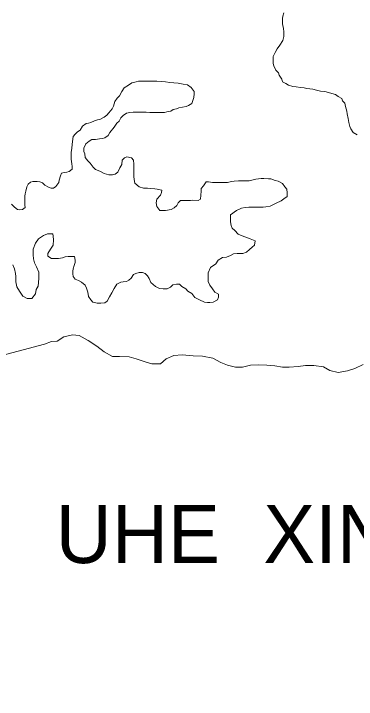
# Model space of a CAD drawing. Extents: x -1643653 to 4543381, y 1624270 to 13878484.
# Drawn here: x 627893 to 630834, y 8933841 to 8939733 of the extents above; entities that cross this region are included whole.
import ezdxf

# ---------------------------------------------------------------- set-up
doc = ezdxf.new("R2010")
doc.units = 0
doc.header["$LTSCALE"] = 200
for name, color, linetype, lineweight in [('25', 7, 'Continuous', 13), ('57', 7, 'Continuous', 13), ('60', 7, 'Continuous', 13)]:
    doc.layers.add(name, color=color, linetype=linetype, lineweight=lineweight)
doc.layers.add('42', color=7, linetype='Continuous')

msp = doc.modelspace()

# ---------------------------------------------------------------- linework, layer by layer
at = {"layer": '25'}
for points in [[(630842.4, 8938690.8), (630807.5, 8938711.1), (630787.8, 8938743.8), (630777.9, 8938763.8), (630770.7, 8938798.9), (630763.5, 8938834), (630756.3, 8938874.1), (630751.4, 8938896.7), (630741.7, 8938934.3), (630734.4, 8938964.4), (630714.6, 8938984.6), (630709.7, 8939004.6), (630677.4, 8939022.4), (630655, 8939040.1), (630625, 8939047.8), (630595.1, 8939055.5), (630562.6, 8939063.2), (630527.6, 8939068.4), (630492.7, 8939076.2), (630460.2, 8939083.9), (630410.3, 8939091.7), (630385.3, 8939096.9), (630355.3, 8939099.6), (630317.8, 8939104.9), (630287.8, 8939107.6), (630252.9, 8939120.3), (630228, 8939133), (630200.6, 8939148.2), (630193.3, 8939170.8), (630171, 8939206), (630166.2, 8939226), (630143.8, 8939248.7), (630126.6, 8939283.9), (630119.2, 8939304), (630119.5, 8939336.5), (630119.7, 8939364), (630137.5, 8939399), (630155.2, 8939431.4), (630178, 8939463.8), (630203.3, 8939503.7), (630211.1, 8939536.2), (630211.3, 8939573.7), (630209.1, 8939608.8), (630204.3, 8939628.8), (630199.4, 8939648.9), (630199.6, 8939668.9), (630199.7, 8939691.5), (630202.4, 8939711.5), (630212.6, 8939741.5)], [(627898.9, 8938069.4), (627926.2, 8938049.2), (627946.2, 8938049), (627968.8, 8938051.4), (627991.4, 8938068.8), (627989.1, 8938088.8), (627986.7, 8938111.4), (627986.9, 8938133.9), (627987.2, 8938166.4), (627989.8, 8938186.4), (627997.5, 8938208.9), (628005.3, 8938243.9), (628015.5, 8938268.9), (628035.6, 8938286.3), (628058.1, 8938291.2), (628093.2, 8938290.9), (628115.6, 8938288.3), (628140.6, 8938280.6), (628160.5, 8938260.4), (628190.3, 8938242.7), (628212.8, 8938232.5), (628232.8, 8938234.9), (628255.4, 8938247.3), (628280.7, 8938282.2), (628283.3, 8938302.2), (628293.6, 8938339.7), (628303.8, 8938362.1), (628326.4, 8938369.5), (628348.9, 8938371.8), (628368.9, 8938376.7), (628394.1, 8938396.6), (628394.3, 8938419.1), (628391.9, 8938441.7), (628389.6, 8938461.7), (628384.7, 8938481.8), (628384.9, 8938501.8), (628385.1, 8938524.3), (628385.2, 8938544.3), (628390.4, 8938574.3), (628393.2, 8938611.9), (628395.9, 8938631.9), (628401.1, 8938656.9), (628403.7, 8938676.9), (628421.4, 8938699.3), (628441.6, 8938716.7), (628461.7, 8938731.6), (628481.9, 8938766.5), (628514.6, 8938788.8), (628534.7, 8938793.7), (628554.7, 8938798.6), (628587.3, 8938813.4), (628612.4, 8938820.7), (628632.4, 8938823.1), (628670.1, 8938842.9), (628692.8, 8938860.2), (628710.4, 8938882.7), (628738.2, 8938915), (628748.4, 8938940), (628761.2, 8938977.5), (628781.4, 8939007.4), (628801.6, 8939027.3), (628821.9, 8939064.7), (628842.1, 8939097.1), (628877.3, 8939119.4), (628907.5, 8939139.2), (628942.6, 8939149), (628965.1, 8939153.9), (628990.1, 8939153.7), (629022.6, 8939153.5), (629062.6, 8939153.2), (629097.7, 8939153), (629122.7, 8939152.8), (629157.7, 8939150.1), (629195.2, 8939147.3), (629232.6, 8939142.1), (629267.6, 8939139.3), (629305.1, 8939136.6), (629347.6, 8939128.8), (629385, 8939121.1), (629417.4, 8939098.3), (629442.1, 8939065.6), (629442, 8939045.6), (629439.2, 8939013), (629431.6, 8938988.1), (629421.3, 8938960.6), (629393.7, 8938943.2), (629373.6, 8938935.9), (629341.1, 8938931.1), (629311, 8938923.8), (629290.9, 8938916.4), (629260.9, 8938909.1), (629240.8, 8938894.2), (629208.2, 8938889.4), (629188.2, 8938884.5), (629155.6, 8938884.7), (629120.6, 8938885), (629093.1, 8938885.2), (629060.6, 8938885.4), (629030.6, 8938885.6), (629010.6, 8938885.7), (628978.1, 8938885.9)], [(628978.1, 8938885.9), (628945.6, 8938886.1), (628918.1, 8938886.3), (628890.5, 8938884), (628860.5, 8938879.2), (628832.8, 8938859.3), (628812.6, 8938836.9), (628797.4, 8938809.5), (628777.3, 8938792.1), (628754.5, 8938757.2), (628719.1, 8938712.4), (628703.9, 8938687.4), (628676.3, 8938667.6), (628656.2, 8938660.2), (628628.7, 8938657.9), (628596.1, 8938653.1), (628563.6, 8938653.3), (628541, 8938638.4), (628510.8, 8938616.1), (628495.5, 8938578.7), (628495.3, 8938548.6), (628502.6, 8938528.5), (628507.4, 8938498.5), (628529.7, 8938468.3), (628549.6, 8938448.1), (628574.3, 8938415.4), (628594.2, 8938395.2), (628631.6, 8938380), (628668.9, 8938359.7), (628708.9, 8938349.4), (628741.4, 8938349.2), (628763.9, 8938354.1), (628786.6, 8938371.4), (628804.4, 8938408.9), (628822.1, 8938436.3), (628824.9, 8938473.8), (628845, 8938493.7), (628865.1, 8938503.6), (628902.6, 8938495.8), (628919.9, 8938473.2), (628924.7, 8938440.6), (628924.5, 8938420.6), (628924.3, 8938393.1), (628924.1, 8938363), (628923.8, 8938333), (628926.2, 8938307.9), (628933.4, 8938277.8), (628970.7, 8938245.1), (629005.6, 8938234.8), (629040.6, 8938234.6), (629063.1, 8938231.9), (629103.1, 8938229.2), (629125.6, 8938224), (629163.1, 8938216.2), (629160.4, 8938196.2), (629152.7, 8938173.8), (629120, 8938138.9), (629114.7, 8938108.9), (629122, 8938076.3), (629146.7, 8938041.1), (629176.7, 8938040.9), (629196.8, 8938043.3), (629244.3, 8938050.5), (629269.5, 8938065.3), (629292.1, 8938085.2), (629304.8, 8938107.7), (629325, 8938127.6), (629347.5, 8938127.4), (629377.5, 8938127.2), (629410, 8938127), (629430, 8938129.3), (629475, 8938129.1), (629497.6, 8938138.9), (629497.9, 8938174), (629500.7, 8938209), (629503.3, 8938231.5), (629521, 8938253.9), (629543.8, 8938288.8), (629566.3, 8938288.7), (629598.8, 8938283.5), (629621.3, 8938283.3), (629656.3, 8938283.1), (629686.3, 8938282.9), (629728.8, 8938282.6), (629763.9, 8938289.9), (629786.4, 8938294.7), (629821.5, 8938297), (629856.5, 8938296.8), (629876.5, 8938296.6), (629914, 8938296.4), (629936.5, 8938301.2), (629971.6, 8938311), (630016.7, 8938315.7), (630039.2, 8938315.6), (630079.2, 8938315.3), (630099.2, 8938315.2), (630136.6, 8938299.9), (630164.1, 8938294.7), (630199, 8938274.5), (630221.2, 8938244.3), (630238.6, 8938224.1)], [(630238.6, 8938224.1), (630240.9, 8938194.1), (630240.6, 8938161.5), (630213, 8938141.7), (630187.8, 8938124.3), (630145.1, 8938104.6), (630094.9, 8938079.9), (630057.4, 8938072.6), (630034.8, 8938070.3), (630004.8, 8938070.5), (629969.8, 8938070.7), (629937.3, 8938070.9), (629912.3, 8938071.1), (629879.7, 8938066.3), (629847.2, 8938061.5), (629804.5, 8938041.8), (629754.2, 8938004.5), (629753.9, 8937969.5), (629753.8, 8937944.5), (629761, 8937914.4), (629768.3, 8937889.3), (629790.7, 8937869.1), (629820.5, 8937838.9), (629855.4, 8937823.6), (629877.8, 8937815.9), (629922.7, 8937798.1), (629965.1, 8937780.3), (629959.8, 8937745.3), (629939.7, 8937725.4), (629917, 8937708), (629891.8, 8937683.2), (629859.2, 8937673.4), (629831.7, 8937671.1), (629811.7, 8937671.2), (629779.2, 8937668.9), (629754.1, 8937656.6), (629718.9, 8937641.8), (629683.9, 8937637), (629648.7, 8937614.7), (629628.4, 8937582.3), (629583.2, 8937552.5), (629562.8, 8937507.6), (629562.6, 8937475.1), (629562.3, 8937432.5), (629577, 8937399.8), (629599.3, 8937369.7), (629619.1, 8937339.5), (629651.5, 8937321.8), (629651.3, 8937296.7), (629641.1, 8937274.2), (629605.9, 8937254.5), (629575.9, 8937252.2), (629555.9, 8937252.3), (629530.9, 8937255), (629488.5, 8937272.8), (629448.7, 8937293.1), (629421.4, 8937328.3), (629386.6, 8937348.5), (629371.7, 8937368.7), (629336.8, 8937388.9), (629317, 8937409.1), (629289.5, 8937409.3), (629259.4, 8937402), (629239.2, 8937382.1), (629209.1, 8937369.7), (629176.6, 8937370), (629144.1, 8937370.2), (629109.2, 8937387.9), (629069.5, 8937423.2), (629054.8, 8937458.4), (629039.9, 8937481), (629022.6, 8937501.2), (628997.6, 8937508.8), (628970.1, 8937509), (628940, 8937501.7), (628919.9, 8937491.8), (628902.2, 8937459.4), (628882.1, 8937442), (628862, 8937432.1), (628831.9, 8937429.8), (628811.9, 8937424.9), (628779.2, 8937407.6), (628754, 8937372.8), (628736.2, 8937335.3), (628715.9, 8937300.4), (628695.6, 8937263), (628675.5, 8937248.1), (628640.5, 8937245.8), (628610.4, 8937246), (628573, 8937253.8), (628555.6, 8937273.9), (628533.3, 8937304.1), (628528.6, 8937339.2), (628516.4, 8937374.3), (628506.6, 8937399.4), (628474.2, 8937427.2), (628449.3, 8937439.9), (628419.4, 8937452.6), (628402.1, 8937475.2), (628399.8, 8937497.8), (628399.9, 8937520.3)], [(627874.1, 8938097.1), (627898.9, 8938069.4)], [(628399.9, 8937520.3), (628402.6, 8937540.3), (628410.3, 8937570.3), (628420.5, 8937595.3), (628420.7, 8937615.3), (628413.4, 8937645.4), (628390.9, 8937648), (628360.9, 8937645.7), (628333.3, 8937643.4), (628310.8, 8937636.1), (628278.2, 8937628.8), (628255.7, 8937628.9), (628218.2, 8937629.2), (628185.8, 8937649.4), (628186, 8937671.9), (628208.8, 8937709.3), (628231.6, 8937744.2), (628234.4, 8937789.3), (628232.2, 8937821.8), (628227.3, 8937841.9), (628207.3, 8937842), (628182.3, 8937842.2), (628147.2, 8937827.4), (628104.4, 8937797.6), (628079.1, 8937760.3), (628058.7, 8937710.3), (628058.3, 8937660.2), (628063.1, 8937627.7), (628070.3, 8937592.6), (628087.6, 8937557.4), (628107.2, 8937512.2), (628109.5, 8937479.7), (628109.3, 8937459.6), (628106.6, 8937422.1), (628101.3, 8937392.1), (628086.1, 8937362.2), (628080.8, 8937324.6), (628048, 8937284.8), (628028, 8937284.9), (628008, 8937285.1), (627970.6, 8937305.3), (627940.9, 8937348.1), (627918.7, 8937385.8), (627911.5, 8937428.4), (627909.4, 8937473.5), (627907.1, 8937501), (627899.9, 8937541.1), (627885.1, 8937573.8)], [(627021.9, 8936878.5), (627718.8, 8936757.5), (627790.7, 8936796.4), (628157.6, 8936893.1), (628218, 8936915.4), (628265.5, 8936920.2), (628323.2, 8936954.9), (628395.9, 8936974.5), (628455.9, 8936966.7)], [(628455.9, 8936966.7), (628533.2, 8936923.8), (628605.5, 8936875.9), (628667.8, 8936828), (628740.2, 8936787.6), (628800.2, 8936787.3), (628885.2, 8936784.3), (628945.2, 8936766.5), (629020.1, 8936741.1), (629077.6, 8936723.3), (629152.6, 8936722.9), (629202.9, 8936767.7), (629266, 8936795.7), (629337.8, 8936802.1), (629403.3, 8936795.7), (629434.6, 8936792.4), (629514.6, 8936789.4), (629602.1, 8936771.5), (629669.5, 8936736.1), (629729.4, 8936713.3), (629796.8, 8936695.4), (629856.9, 8936695.1), (629924.5, 8936712.3), (629997.1, 8936714.4), (630067.1, 8936714), (630134.6, 8936706.2), (630199.6, 8936695.8), (630257.1, 8936695.5), (630334.7, 8936702.6), (630397.3, 8936709.8), (630469.8, 8936709.4), (630552.3, 8936699), (630607.2, 8936666.2), (630677.2, 8936650.8), (630759.8, 8936665.4), (630822.5, 8936685.1), (630892.7, 8936719.7)]]:
    msp.add_lwpolyline(points, dxfattribs=at)
at = {"layer": '57'}
for points in [[(630842.4, 8938690.8), (630807.5, 8938711.1), (630787.8, 8938743.8), (630777.9, 8938763.8), (630770.7, 8938798.9), (630763.5, 8938834), (630756.3, 8938874.1), (630751.4, 8938896.7), (630741.7, 8938934.3), (630734.4, 8938964.4), (630714.6, 8938984.6), (630709.7, 8939004.6), (630677.4, 8939022.4), (630655, 8939040.1), (630625, 8939047.8), (630595.1, 8939055.5), (630562.6, 8939063.2), (630527.6, 8939068.4), (630492.7, 8939076.2), (630460.2, 8939083.9), (630410.3, 8939091.7), (630385.3, 8939096.9), (630355.3, 8939099.6), (630317.8, 8939104.9), (630287.8, 8939107.6), (630252.9, 8939120.3), (630228, 8939133), (630200.6, 8939148.2), (630193.3, 8939170.8), (630171, 8939206), (630166.2, 8939226), (630143.8, 8939248.7), (630126.6, 8939283.9), (630119.2, 8939304), (630119.5, 8939336.5), (630119.7, 8939364), (630137.5, 8939399), (630155.2, 8939431.4), (630178, 8939463.8), (630203.3, 8939503.7), (630211.1, 8939536.2), (630211.3, 8939573.7), (630209.1, 8939608.8), (630204.3, 8939628.8), (630199.4, 8939648.9), (630199.6, 8939668.9), (630199.7, 8939691.5), (630202.4, 8939711.5), (630212.6, 8939741.5)], [(630212.6, 8939741.5), (630202.4, 8939711.5), (630199.7, 8939691.5), (630199.6, 8939668.9), (630199.4, 8939648.9), (630204.3, 8939628.8), (630209.1, 8939608.8), (630211.3, 8939573.7), (630211.1, 8939536.2), (630203.3, 8939503.7), (630178, 8939463.8), (630155.2, 8939431.4), (630137.5, 8939399), (630119.7, 8939364), (630119.5, 8939336.5), (630119.2, 8939304), (630126.6, 8939283.9), (630143.8, 8939248.7), (630166.2, 8939226), (630171, 8939206), (630193.3, 8939170.8), (630200.6, 8939148.2), (630228, 8939133), (630252.9, 8939120.3), (630287.8, 8939107.6), (630317.8, 8939104.9), (630355.3, 8939099.6), (630385.3, 8939096.9), (630410.3, 8939091.7), (630460.2, 8939083.9), (630492.7, 8939076.2), (630527.6, 8939068.4), (630562.6, 8939063.2), (630595.1, 8939055.5), (630625, 8939047.8), (630655, 8939040.1), (630677.4, 8939022.4), (630709.7, 8939004.6), (630714.6, 8938984.6), (630734.4, 8938964.4), (630741.7, 8938934.3), (630751.4, 8938896.7), (630756.3, 8938874.1), (630763.5, 8938834), (630770.7, 8938798.9), (630777.9, 8938763.8), (630787.8, 8938743.8), (630807.5, 8938711.1), (630842.4, 8938690.8)]]:
    msp.add_lwpolyline(points, dxfattribs=at)
at = {"layer": '60', "lineweight": 25}
msp.add_spline([(814781, 9009175.5), (814787.2, 9009173.4), (814796.9, 9009173.4), (814799.4, 9009172.4), (814805.1, 9009174.5), (814805.6, 9009176.5), (814811.7, 9009179.5), (814811.7, 9009179.5), (814801.5, 9009181), (814790.7, 9009181.5), (814784.1, 9009183.1), (814777.4, 9009185.1), (814778.4, 9009175.5)], degree=3, dxfattribs=at)

# ---------------------------------------------------------------- texts
at = {"layer": '42'}
msp.add_text('UHE  XINGÓ', height=500, dxfattribs=at).set_placement((628251.9, 8935011.6))

doc.saveas('drawing.dxf')
